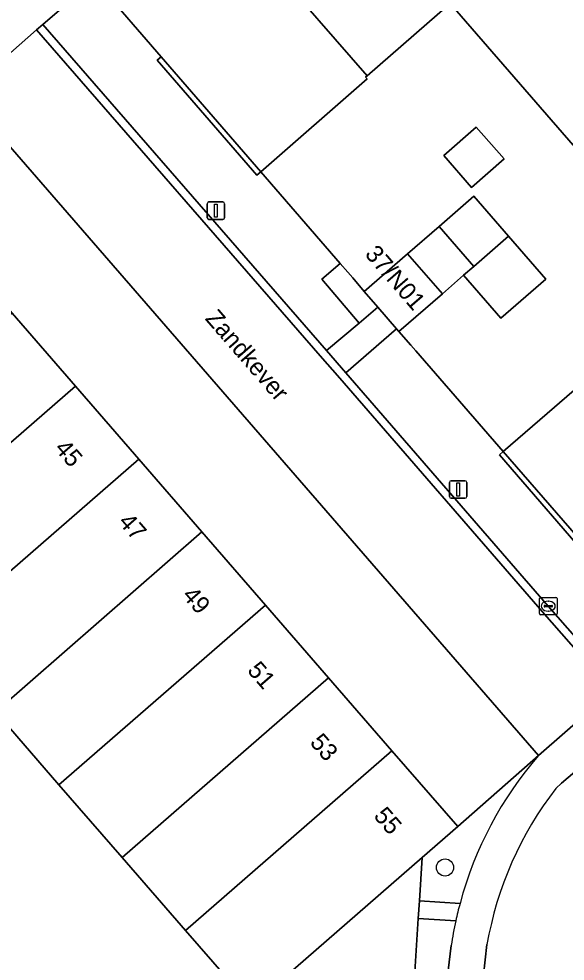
# Model space of a CAD drawing. Extents: x 155887 to 156869, y 383880 to 384678.
# Drawn here: x 156045 to 156076.2, y 384007.6 to 384061.3 of the extents above; entities that cross this region are included whole.
import ezdxf

# ---------------------------------------------------------------- set-up
doc = ezdxf.new("R2010")
doc.units = 0
for name, color, linetype in [('IMGEO_Boom', 7, 'Continuous'), ('IMGEO_Erf', 7, 'Continuous'), ('IMGEO_Grasland_overig', 7, 'Continuous'), ('IMGEO_Groenvoorziening', 7, 'Continuous'), ('IMGEO_Hek', 7, 'Continuous'), ('IMGEO_Kolk', 7, 'Continuous'), ('IMGEO_Lichtmast', 7, 'Continuous'), ('IMGEO_Openbare_ruimte_label', 7, 'Continuous'), ('IMGEO_Pand', 7, 'Continuous'), ('IMGEO_Pand_nummerreeks', 7, 'Continuous'), ('IMGEO_Rijbaan_lokaal_gesloten', 7, 'Continuous'), ('IMGEO_Rijbaan_lokaal_open', 7, 'Continuous'), ('IMGEO_Voetpad_open', 7, 'Continuous')]:
    doc.layers.add(name, color=color, linetype=linetype)

msp = doc.modelspace()

# ---------------------------------------------------------------- linework, layer by layer
at = {"layer": 'IMGEO_Boom'}
msp.add_circle((156069.316, 384012.903), 0.489, dxfattribs=at)
at = {"layer": 'IMGEO_Erf'}
for points in [[(156076.634, 384054.1), (156069.611, 384062.178), (156064.865, 384058.052), (156064.781, 384057.979), (156064.866, 384057.881), (156058.812, 384052.584), (156063.335, 384047.351), (156063.766, 384046.853), (156064.051, 384046.542), (156064.711, 384045.761), (156067.182, 384047.909), (156068.981, 384049.473), (156070.965, 384051.197), (156072.945, 384048.919), (156075.06, 384046.465), (156072.5, 384044.238), (156070.374, 384046.682), (156069.164, 384045.629), (156066.689, 384043.476), (156067.366, 384042.692), (156067.649, 384042.38), (156072.643, 384036.633), (156078.781, 384041.936)], [(155998.041, 384016.855), (156002.964, 384011.173), (156002.615, 384006.624), (156067.288, 384002.076), (156067.79, 384009.998), (156067.854, 384010.996), (156068.011, 384013.475), (156058.272, 384004.999), (156054.512, 384009.319), (156050.896, 384013.474), (156047.286, 384017.621), (156043.663, 384021.784)]]:
    msp.add_lwpolyline(points, dxfattribs=at)
for points in [[(156041.863, 384057.029), (156037.26, 384052.977), (156041, 384048.672), (156044.612, 384044.514), (156048.224, 384040.356), (156051.837, 384036.198), (156055.449, 384032.039), (156059.068, 384027.874), (156062.673, 384023.724), (156066.285, 384019.566), (156070.039, 384015.245), (156074.654, 384019.297)], [(156070.835, 384051.697), (156069.241, 384053.52), (156071.089, 384055.136), (156072.683, 384053.314)]]:
    msp.add_lwpolyline(points, close=True, dxfattribs=at)
at = {"layer": 'IMGEO_Grasland_overig'}
for points in [[(156052.894, 384058.954), (156058.586, 384052.388), (156058.812, 384052.584), (156053.12, 384059.15)], [(156072.417, 384036.437), (156078.109, 384029.871), (156078.335, 384030.067), (156072.643, 384036.633)]]:
    msp.add_lwpolyline(points, close=True, dxfattribs=at)
at = {"layer": 'IMGEO_Groenvoorziening'}
for points in [[(156052.894, 384058.954), (156053.12, 384059.15), (156049.556, 384063.26), (156049.308, 384063.528), (156046.361, 384060.988), (156062.547, 384042.389), (156064.409, 384043.953), (156062.297, 384046.467), (156063.335, 384047.351), (156058.812, 384052.584), (156058.586, 384052.388)], [(156081.898, 384025.956), (156078.335, 384030.067), (156078.109, 384029.871), (156072.417, 384036.437), (156072.643, 384036.633), (156067.649, 384042.38), (156067.366, 384042.692), (156066.689, 384043.476), (156066.553, 384043.627), (156063.655, 384041.108), (156075.21, 384027.812), (156079.199, 384023.268), (156082.073, 384025.755)]]:
    msp.add_lwpolyline(points, close=True, dxfattribs=at)
for points in [[(156074.654, 384019.297), (156070.039, 384015.245), (156068.011, 384013.475), (156067.854, 384010.996), (156070.172, 384010.849)], [(156069.931, 384009.862), (156067.79, 384009.998), (156067.288, 384002.076), (156068.886, 384001.964), (156069.673, 384008.462)]]:
    msp.add_lwpolyline(points, dxfattribs=at)
for centre, radius, start, end in [((156090.878, 384005.277), 21.443, 139.1672, 164.9373), ((156090.277, 384005.389), 20.832, 167.6003, 171.5164)]:
    msp.add_arc(centre, radius, start, end, dxfattribs=at)
at = {"layer": 'IMGEO_Hek'}
for points in [[(156068.011, 384013.475), (156067.854, 384010.996)], [(156067.854, 384010.996), (156067.79, 384009.998)], [(156067.79, 384009.998), (156067.288, 384002.076)]]:
    msp.add_lwpolyline(points, dxfattribs=at)
at = {"layer": 'IMGEO_Kolk'}
for p, q in [((156074.708, 384027.385), (156074.708, 384028.237)), ((156074.783, 384028.311), (156075.635, 384028.311)), ((156075.709, 384028.237), (156075.709, 384027.385)), ((156074.967, 384027.805), (156074.967, 384027.817)), ((156075.405, 384027.768), (156075.007, 384027.768)), ((156075.01, 384027.854), (156075.408, 384027.854)), ((156075.196, 384028.091), (156075.221, 384028.091)), ((156075.451, 384027.817), (156075.451, 384027.805)), ((156075.635, 384027.311), (156074.783, 384027.311)), ((156075.219, 384027.531), (156075.194, 384027.531))]:
    msp.add_line(p, q, dxfattribs=at)
for points in [[(156074.708, 384027.385), (156074.708, 384028.237)], [(156074.783, 384028.311), (156075.635, 384028.311)], [(156075.709, 384028.237), (156075.709, 384027.385)], [(156075.635, 384027.311), (156074.783, 384027.311)]]:
    msp.add_lwpolyline(points, dxfattribs=at)
for centre, radius, start, end in [((156074.785, 384028.235), 0.0765, 91.552, 178.448), ((156074.785, 384028.235), 0.0765, 91.552, 178.448), ((156075.633, 384028.235), 0.0765, 1.552, 88.448), ((156075.633, 384028.235), 0.0765, 1.552, 88.448), ((156075.007, 384027.814), 0.0403, 85.8775, 175.7526), ((156075.004, 384027.804), 0.0366, 178.938, 274.7102), ((156075.408, 384027.811), 0.043, 264.8664, 352.4533), ((156075.412, 384027.816), 0.0386, 1.7309, 96.639), ((156074.785, 384027.387), 0.0765, 181.552, 268.448), ((156074.785, 384027.387), 0.0765, 181.552, 268.448), ((156075.633, 384027.387), 0.0765, 271.552, 358.448), ((156075.633, 384027.387), 0.0765, 271.552, 358.448)]:
    msp.add_arc(centre, radius, start, end, dxfattribs=at)
for centre, major_axis, ratio, start_param, end_param in [((156075.195, 384027.811), (-0.387, 0.002), 0.722429, 4.712389, 7.853982), ((156075.22, 384027.811), (-0.39, 0.002), 0.717154, 1.570796, 4.712389)]:
    msp.add_ellipse(centre, major_axis=major_axis, ratio=ratio, start_param=start_param, end_param=end_param, dxfattribs=at)
at = {"layer": 'IMGEO_Lichtmast'}
for p, q in [((156055.746, 384049.963), (156055.746, 384050.763)), ((156055.746, 384050.763), (156055.746, 384049.963)), ((156055.846, 384050.863), (156056.636, 384050.863)), ((156056.636, 384050.863), (156055.846, 384050.863)), ((156056.736, 384050.763), (156056.736, 384049.963)), ((156056.736, 384049.963), (156056.736, 384050.763)), ((156056.636, 384049.863), (156055.846, 384049.863)), ((156055.846, 384049.863), (156056.636, 384049.863)), ((156069.565, 384034.061), (156069.565, 384034.861)), ((156069.565, 384034.861), (156069.565, 384034.061)), ((156069.665, 384034.961), (156070.455, 384034.961)), ((156070.455, 384034.961), (156069.665, 384034.961)), ((156070.555, 384034.861), (156070.555, 384034.061)), ((156070.555, 384034.061), (156070.555, 384034.861)), ((156070.455, 384033.961), (156069.665, 384033.961)), ((156069.665, 384033.961), (156070.455, 384033.961))]:
    msp.add_line(p, q, dxfattribs=at)
for points in [[(156056.166, 384050.738), (156056.316, 384050.738), (156056.316, 384049.988), (156056.166, 384049.988), (156056.166, 384050.738)], [(156069.985, 384034.836), (156070.135, 384034.836), (156070.135, 384034.086), (156069.985, 384034.086), (156069.985, 384034.836)]]:
    msp.add_lwpolyline(points, dxfattribs=at)
for centre, start, end in [((156055.846, 384050.763), 90, 180), ((156055.846, 384050.763), 90, 180), ((156056.636, 384050.763), 0, 90), ((156056.636, 384050.763), 360, 90), ((156055.846, 384049.963), 180, 270), ((156055.846, 384049.963), 180, 270), ((156056.636, 384049.963), 270, 0), ((156056.636, 384049.963), 270, 0), ((156069.665, 384034.861), 90, 180), ((156069.665, 384034.861), 90, 180), ((156070.455, 384034.861), 0, 90), ((156070.455, 384034.861), 360, 90), ((156069.665, 384034.061), 180, 270), ((156069.665, 384034.061), 180, 270), ((156070.455, 384034.061), 270, 0), ((156070.455, 384034.061), 270, 0)]:
    msp.add_arc(centre, 0.1, start, end, dxfattribs=at)
at = {"layer": 'IMGEO_Pand'}
for points in [[(156073.018, 384067.03), (156072.89, 384066.918), (156070.305, 384069.888), (156068.375, 384068.213), (156066.298, 384070.606), (156063.276, 384067.981), (156059.917, 384071.845), (156059.7, 384072.094), (156055.688, 384068.606), (156059.264, 384064.493), (156064.865, 384058.052), (156069.611, 384062.178), (156076.634, 384054.1), (156080.993, 384057.855), (156079.995, 384059.003)], [(156059.264, 384064.493), (156059.104, 384064.354), (156057.925, 384063.329), (156056.148, 384061.784), (156052.561, 384065.887), (156049.556, 384063.26), (156053.12, 384059.15), (156058.812, 384052.584), (156064.866, 384057.881), (156064.781, 384057.979), (156064.865, 384058.052)], [(156070.835, 384051.697), (156072.683, 384053.314), (156071.089, 384055.136), (156069.241, 384053.52)], [(156070.957, 384047.189), (156072.945, 384048.919), (156070.965, 384051.197), (156068.981, 384049.473)], [(156068.981, 384049.473), (156067.182, 384047.909), (156069.164, 384045.629), (156070.374, 384046.682), (156070.957, 384047.189)], [(156072.945, 384048.919), (156070.957, 384047.189), (156070.374, 384046.682), (156072.5, 384044.238), (156075.06, 384046.465)], [(156067.182, 384047.909), (156064.711, 384045.761), (156065.488, 384044.86), (156066.553, 384043.627), (156066.689, 384043.476), (156069.164, 384045.629)], [(156032.814, 384034.249), (156036.43, 384030.094), (156048.224, 384040.356), (156044.612, 384044.514)], [(156084.325, 384035.31), (156084.509, 384035.47), (156079.905, 384040.792), (156078.781, 384041.936), (156072.643, 384036.633), (156078.335, 384030.067), (156081.898, 384025.956), (156084.955, 384028.622), (156081.373, 384032.729), (156081.904, 384033.194)], [(156051.837, 384036.198), (156048.224, 384040.356), (156036.43, 384030.094), (156040.047, 384025.939)], [(156051.837, 384036.198), (156040.047, 384025.939), (156043.663, 384021.784), (156055.449, 384032.039)], [(156043.663, 384021.784), (156047.286, 384017.621), (156059.068, 384027.874), (156055.449, 384032.039)], [(156062.673, 384023.724), (156059.068, 384027.874), (156047.286, 384017.621), (156050.896, 384013.474)], [(156062.673, 384023.724), (156050.896, 384013.474), (156054.512, 384009.319), (156066.285, 384019.566)], [(156066.285, 384019.566), (156054.512, 384009.319), (156058.272, 384004.999), (156068.011, 384013.475), (156070.039, 384015.245)]]:
    msp.add_lwpolyline(points, close=True, dxfattribs=at)
at = {"layer": 'IMGEO_Rijbaan_lokaal_gesloten'}
for points in [[(156220.023, 384134.972), (156222.856, 384137.431), (156224.147, 384138.552), (156223.837, 384138.892), (156220.134, 384142.954), (156131.822, 384066.268), (156079.811, 384021.104), (156077.481, 384019.012), (156075.96, 384017.712), (156075.644, 384017.414)], [(156071.711, 384008.503), (156071.133, 384003.262), (156071.547, 384003.196), (156071.477, 384002.639)]]:
    msp.add_lwpolyline(points, dxfattribs=at)
msp.add_arc((156091.604, 384005.046), 20.191, 142.2272, 170.1429, dxfattribs=at)
at = {"layer": 'IMGEO_Rijbaan_lokaal_open'}
for points in [[(156079.199, 384023.268), (156075.21, 384027.812), (156063.655, 384041.108), (156062.547, 384042.389), (156046.361, 384060.988), (156046.015, 384060.684), (156062.199, 384042.088), (156063.308, 384040.806), (156074.863, 384027.509), (156078.852, 384022.966)], [(156046.015, 384060.684), (156041.863, 384057.029), (156074.654, 384019.297), (156078.852, 384022.966), (156074.863, 384027.509), (156063.308, 384040.806), (156062.199, 384042.088)]]:
    msp.add_lwpolyline(points, close=True, dxfattribs=at)
at = {"layer": 'IMGEO_Voetpad_open'}
for points in [[(156000, 384020.578), (156001.423, 384021.932), (156025.456, 384042.703), (156037.26, 384052.977), (156041.863, 384057.029), (156046.015, 384060.684), (156046.361, 384060.988), (156049.308, 384063.528), (156064.539, 384076.733), (156096.561, 384104.495), (156097.741, 384105.518), (156096.403, 384107.059), (156096.361, 384107.023), (156095.22, 384106.032), (156000.779, 384024.065), (156000, 384023.453)], [(156075.644, 384017.414), (156075.96, 384017.712), (156077.481, 384019.012), (156079.811, 384021.104), (156131.822, 384066.268), (156130.502, 384067.788), (156120.993, 384059.536), (156116.175, 384055.356), (156106.978, 384047.376), (156102.161, 384043.195), (156092.905, 384035.164), (156088.272, 384031.12), (156088.111, 384030.979), (156082.073, 384025.755), (156079.199, 384023.268), (156078.852, 384022.966), (156074.654, 384019.297)], [(156070.172, 384010.849), (156067.854, 384010.996), (156067.79, 384009.998), (156069.931, 384009.862)], [(156069.673, 384008.462), (156068.886, 384001.964), (156068.651, 384000.027), (156070.88, 383999.85)], [(156071.477, 384002.639), (156071.547, 384003.196), (156071.133, 384003.262), (156071.711, 384008.503)]]:
    msp.add_lwpolyline(points, dxfattribs=at)
for points in [[(156064.711, 384045.761), (156064.051, 384046.542), (156063.766, 384046.853), (156063.335, 384047.351), (156062.297, 384046.467), (156064.409, 384043.953), (156065.488, 384044.86)], [(156066.553, 384043.627), (156065.488, 384044.86), (156064.409, 384043.953), (156062.547, 384042.389), (156063.655, 384041.108)]]:
    msp.add_lwpolyline(points, close=True, dxfattribs=at)
for centre, radius, start, end in [((156090.878, 384005.277), 21.443, 139.1672, 164.9373), ((156091.604, 384005.046), 20.191, 142.2272, 170.1429), ((156092.044, 384004.985), 22.645, 164.9929, 167.5638), ((156092.044, 384004.985), 22.645, 164.9929, 167.5638), ((156090.277, 384005.389), 20.832, 167.6003, 171.5164)]:
    msp.add_arc(centre, radius, start, end, dxfattribs=at)

# ---------------------------------------------------------------- texts
at = {"layer": 'IMGEO_Openbare_ruimte_label'}
msp.add_text('Zandkever', height=1, rotation=310.9865, dxfattribs=at).set_placement((156055.587, 384044.187))
at = {"layer": 'IMGEO_Pand_nummerreeks'}
for s, rotation, p in [('37/N01', 310.8335, (156064.698, 384047.861)), ('45', 310.9819, (156046.99, 384036.777)), ('47', 310.9819, (156050.632, 384032.584)), ('49', 310.9819, (156054.274, 384028.392)), ('51', 310.9819, (156057.99, 384024.114)), ('53', 310.9819, (156061.559, 384020.007)), ('55', 310.9819, (156065.201, 384015.814))]:
    msp.add_text(s, height=1, rotation=rotation, dxfattribs=at).set_placement(p)

doc.saveas('drawing.dxf')
